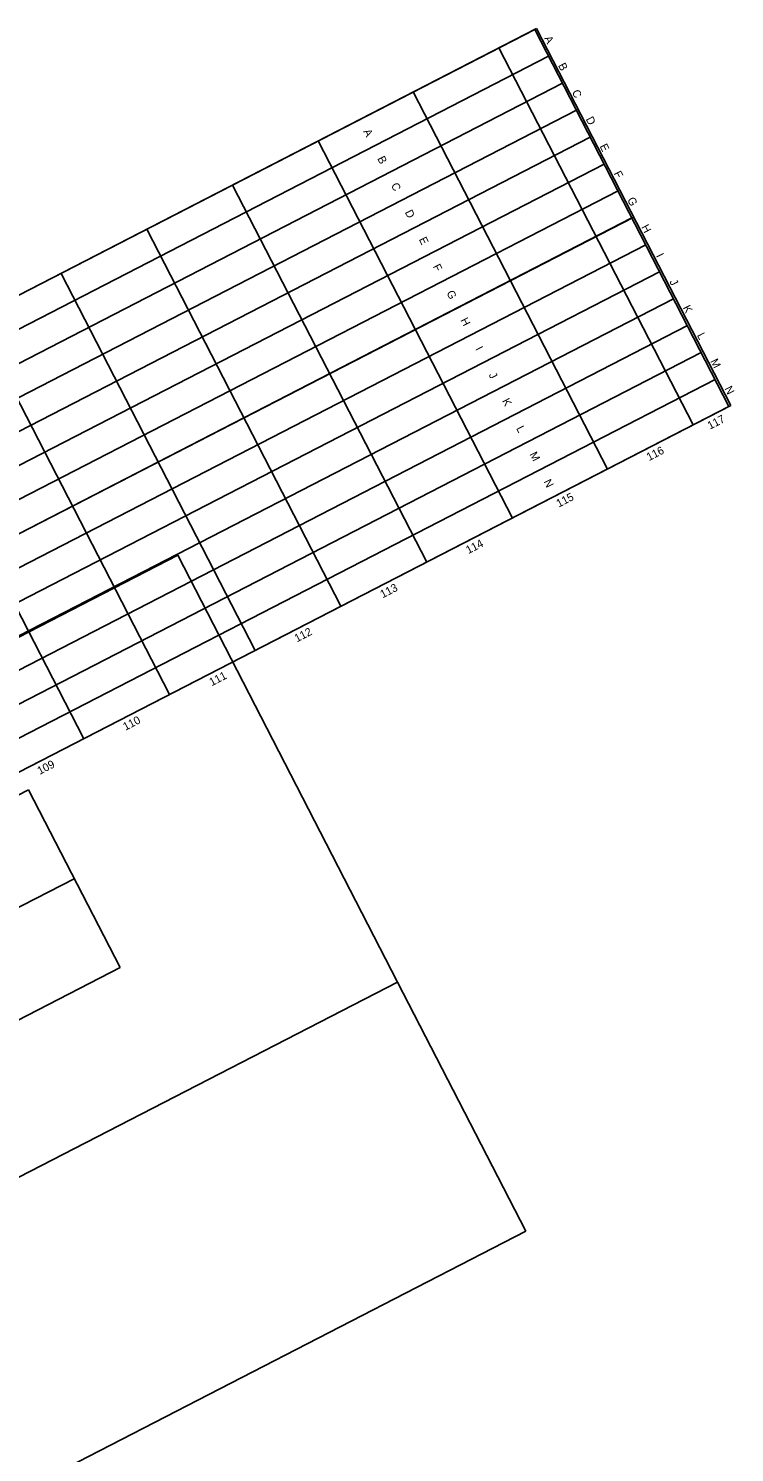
# Model space of a CAD drawing. Extents: x -886320 to -884760, y -1024172 to -1023483.
# Drawn here: x -884848.5 to -884760.3, y -1023661.3 to -1023483.3 of the extents above; entities that cross this region are included whole.
import ezdxf

# ---------------------------------------------------------------- set-up
doc = ezdxf.new("R2010")
doc.units = 0
for name, color, linetype in [('AGA__Netisknout', 7, 'Continuous'), ('Stavajici_betonova_draha', 7, 'Continuous'), ('Stavajici_betonova_draha_osa', 7, 'Continuous'), ('Stavajici_betonova_draha_Popis desky', 7, 'Continuous'), ('Stavajici_betonova_draha_Spára', 7, 'Continuous'), ('Stavajici_drahovy_system', 7, 'Continuous'), ('Stavajici_drahovy_system_osy', 7, 'Continuous'), ('Stavajici_drahovy_system_RWY_strip', 7, 'Continuous')]:
    doc.layers.add(name, color=color, linetype=linetype)

msp = doc.modelspace()

# ---------------------------------------------------------------- linework, layer by layer
at = {"layer": 'AGA__Netisknout'}
msp.add_line((-886017.78, -1024147.99), (-884773.13, -1023507.02), dxfattribs=at)
at = {"layer": 'Stavajici_betonova_draha'}
for p, q in [((-886029.69, -1024124.32), (-884785.04, -1023483.35)), ((-886029.69, -1024124.32), (-884785.04, -1023483.35)), ((-884785.04, -1023483.35), (-884760.77, -1023530.47)), ((-884785.04, -1023483.35), (-884760.77, -1023530.47)), ((-886005.42, -1024171.44), (-884760.77, -1023530.47)), ((-886005.42, -1024171.44), (-884760.77, -1023530.47))]:
    msp.add_line(p, q, dxfattribs=at)
at = {"layer": 'Stavajici_betonova_draha_osa'}
msp.add_line((-886017.55, -1024147.88), (-884772.9, -1023506.91), dxfattribs=at)
at = {"layer": 'Stavajici_betonova_draha_Spára'}
for p, q in [((-886029.91, -1024124.43), (-884785.26, -1023483.46)), ((-884785.26, -1023483.46), (-884760.99, -1023530.58)), ((-884789.74, -1023485.77), (-884765.47, -1023532.89)), ((-886028.18, -1024127.8), (-884783.53, -1023486.82)), ((-886026.44, -1024131.16), (-884781.79, -1023490.19)), ((-884800.45, -1023491.28), (-884776.19, -1023538.41)), ((-886024.71, -1024134.53), (-884780.06, -1023493.56)), ((-886022.98, -1024137.89), (-884778.33, -1023496.92)), ((-884812.32, -1023497.4), (-884788.06, -1023544.52)), ((-886021.24, -1024141.26), (-884776.59, -1023500.29)), ((-886019.51, -1024144.63), (-884774.86, -1023503.65)), ((-884823.04, -1023502.91), (-884798.77, -1023550.03)), ((-884833.75, -1023508.43), (-884809.48, -1023555.55)), ((-886016.04, -1024151.36), (-884771.39, -1023510.39)), ((-886014.31, -1024154.72), (-884769.66, -1023513.75)), ((-884844.46, -1023513.95), (-884820.19, -1023561.07)), ((-886012.58, -1024158.09), (-884767.93, -1023517.12)), ((-884855.17, -1023519.46), (-884830.91, -1023566.59)), ((-886010.84, -1024161.46), (-884766.19, -1023520.48)), ((-886009.11, -1024164.82), (-884764.46, -1023523.85)), ((-884865.89, -1023524.98), (-884841.62, -1023572.1)), ((-886007.38, -1024168.19), (-884762.73, -1023527.21)), ((-886005.64, -1024171.55), (-884760.99, -1023530.58))]:
    msp.add_line(p, q, dxfattribs=at)
at = {"layer": 'Stavajici_drahovy_system'}
for p, q in [((-884864.53, -1023586.71), (-884848.53, -1023578.47)), ((-884848.53, -1023578.47), (-884837.08, -1023600.7)), ((-885726.12, -1024058.54), (-884837.08, -1023600.7)), ((-885744.78, -1024087.83), (-884802.4, -1023602.52)), ((-884802.4, -1023602.52), (-884786.38, -1023633.64)), ((-885728.75, -1024118.95), (-884786.38, -1023633.64))]:
    msp.add_line(p, q, dxfattribs=at)
at = {"layer": 'Stavajici_drahovy_system_osy'}
msp.add_line((-885731.84, -1024047.42), (-884842.81, -1023589.59), dxfattribs=at)
at = {"layer": 'Stavajici_drahovy_system_RWY_strip'}
for p, q in [((-885772.25, -1024034.49), (-884829.87, -1023549.18)), ((-884829.87, -1023549.18), (-884802.4, -1023602.52)), ((-884802.4, -1023602.52), (-885744.78, -1024087.83))]:
    msp.add_line(p, q, dxfattribs=at)

# ---------------------------------------------------------------- texts
at = {"layer": 'Stavajici_betonova_draha_Popis desky'}
for s, rotation, p in [('A', 297.2477, (-884784.12, -1023484.57)), ('B', 297.2477, (-884782.38, -1023487.96)), ('C', 297.2477, (-884780.66, -1023491.3)), ('D', 297.2477, (-884778.92, -1023494.67)), ('A', 297.2477, (-884806.72, -1023496.21)), ('E', 297.2477, (-884777.18, -1023498.06)), ('B', 297.2477, (-884804.97, -1023499.6)), ('F', 297.2477, (-884775.43, -1023501.45)), ('C', 297.2477, (-884803.26, -1023502.93)), ('G', 297.2477, (-884773.74, -1023504.74)), ('D', 297.2477, (-884801.52, -1023506.31)), ('H', 297.2477, (-884771.98, -1023508.15)), ('E', 297.2477, (-884799.77, -1023509.7)), ('I', 297.2477, (-884770.13, -1023511.74)), ('F', 297.2477, (-884798.03, -1023513.09)), ('G', 297.2477, (-884796.33, -1023516.38)), ('J', 297.2477, (-884768.46, -1023514.99)), ('K', 297.2477, (-884766.79, -1023518.23)), ('H', 297.2477, (-884794.58, -1023519.79)), ('L', 297.2477, (-884765.02, -1023521.67)), ('I', 297.2477, (-884792.73, -1023523.38)), ('M', 297.2477, (-884763.35, -1023524.92)), ('J', 297.2477, (-884791.05, -1023526.63)), ('N', 297.2477, (-884761.58, -1023528.34)), ('K', 297.2477, (-884789.38, -1023529.87)), ('117', 27.2477, (-884763.37, -1023533.49)), ('L', 297.2477, (-884787.61, -1023533.31)), ('116', 27.2477, (-884770.98, -1023537.41)), ('M', 297.2477, (-884785.94, -1023536.55)), ('N', 297.2477, (-884784.18, -1023539.98)), ('115', 27.2477, (-884782.26, -1023543.22)), ('114', 27.2477, (-884793.56, -1023549.04)), ('113', 27.2477, (-884804.27, -1023554.56)), ('112', 27.2477, (-884814.98, -1023560.07)), ('111', 27.2477, (-884825.63, -1023565.55)), ('110', 27.2477, (-884836.41, -1023571.11)), ('109', 27.2477, (-884847.12, -1023576.62))]:
    msp.add_text(s, height=1, rotation=rotation, dxfattribs=at).set_placement(p)

doc.saveas('drawing.dxf')
